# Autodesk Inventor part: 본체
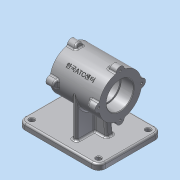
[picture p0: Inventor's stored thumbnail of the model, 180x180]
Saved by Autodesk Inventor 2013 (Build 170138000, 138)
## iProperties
Created: 2015-12
Part Number: 본체
Material: 알루미늄 6061
Document SubType Name: Modeling
Designer: dgall
Density: 2.71 g/cm^3
Mass: 1163.86 g
Surface Area: 818.799 cm^2
Volume: 429.47 cm^3
Author: dgall
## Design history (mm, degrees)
sketch "스케치1"
  geometry: C1 r 37 at (0, 0); 1 further point
  constraints: 1 centre point, 1 coincident
  dimensions: "d0" = 74 diameter of C1
extrude "돌출1" new body sketch "스케치1" stored distance "d1" = 85; taper "d2" = 0 deg
sketch "스케치2"
  geometry: L1 (0, 42.5)-(0, -42.5); L2 (0, 42.5)-(23.5, 42.5); L3 (23.5, 42.5)-(23.5, 20.5); L4 (23.5, 20.5)-(21, 20.5); L5 (21, 20.5)-(21, -20.5); L6 (21, -20.5)-(23.5, -20.5); L7 (23.5, -20.5)-(23.5, -42.5); L8 (23.5, -42.5)-(0, -42.5); 2 further points
  constraints: 16 end point, 4 parallel, 2 perpendicular, 1 coincident, 1 collinear, 1 midpoint, 1 vertical
  dimensions: "d3" = 85 distance of L1.start L1.end; "d5" = 47 diameter of L3 L1; "d6" = 47 diameter of L7 L1; "d7" = 42 diameter of L5 L1; "d8" = 22 distance of L2.end L3.end; "d9" = 22 distance of L6.end L7.end
revolve "회전1" sketch "스케치2" stored, may be unused: angle "d10" = 90 deg
sketch "스케치3"
  geometry: C1 r 23.5 at (0, 0) reference; C2 r 7 at (0, 37); 1 further point
  constraints: 2 vertical alignment, 1 centre point, 1 other
  dimensions: "d11" = 14 diameter of C2
node "작업 평면1"
sketch "스케치4"
  geometry: L1 (55, 80)-(-55, 80); L2 (-55, 80)-(-55, -60); L3 (-55, -60)-(55, -60); L4 (55, -60)-(55, 80); L5 (37, 4)-(-37, 4); L6 (-37, 4)-(-37, -4); L7 (-37, -4)-(37, -4); L8 (37, -4)-(37, 4); 5 further points
  constraints: 16 end point, 4 midpoint, 4 parallel, 2 horizontal, 2 perpendicular, 2 vertical alignment, 1 horizontal alignment
  dimensions: "d13" = 140 distance of L3.end L1.start; "d15" = 110 distance of L2.end L3.end; "d16" = 8 distance of L7.end L5.start; "d17" = 76 distance between parallel lines of L1 L5; "d18" = 74 distance of L6.end L7.end
extrude "돌출2" join sketch "스케치4" distance "d19" = 10; taper "d20" = 0 deg
extrude "돌출3" join sketch "스케치4" stored distance "d21" = 10; taper "d22" = 0 deg
sketch "스케치5"
  geometry: L1 (-70, -60)-(-70, 80) reference; L2 (-37, 20.948)-(-70, 25); L3 (-37, -20.948)-(-70, -25); L4 (37, 42.5)-(-37, 42.5) reference; 2 further points
  constraints: 4 end point, 2 point on line
  dimensions: "d24" = 50 distance of L3.end L2.end; "d25" = 21 distance of point (-70, 4) L2.end; "d26" = 97 deg angle of L1 L2; "d27" = 97 deg angle of L1 L3
feature "리브1" sketch "스케치5" dims "d28" = 1, "d29" = 12, "d30" = 0, "d31" = 0, "d32" = 1, "d33" = 1
node "작업 평면3"
extrude "돌출4" join sketch "스케치3" distance "d34" = 12.452; taper "d35" = 0 deg
sketch "스케치7"
  geometry: L1 (44, 42.5)-(44, 30.048) reference; L2 (37, -42.5)-(37, 30.048) reference; L3 (44, 30.048)-(34, 26.408); L4 (34, 30.5)-(44, 30.5); L5 (34, 30.5)-(34, 26.408); 2 further points
  constraints: 6 end point, 3 point on line, 2 perpendicular
  dimensions: "d41" = 110 deg angle of L2 L3; "d76" = 4.09191 distance of L4.start L3.end; "d78" = 10 distance of L4.start L4.end
extrude "돌출5" join sketch "스케치7" stored distance "d44" = 14; taper "d45" = 0 deg
sketch "스케치8"
  geometry: L1 (-9, 45)-(9, 45); L2 (9, 45)-(9, 35.889); L3 (-9, 35.889)-(-9, 45); C1 r 23.5 at (0, 0) reference; A1 r 7 centre (0, 37) between (6.969, 36.338) and (-6.969, 36.338) reference; A2 r 7 centre (0, 37) between (6.969, 36.338) and (-6.969, 36.338); A3 r 37 centre (0, 0) between (9, 35.889) and (6.969, 36.338); A4 r 37 centre (0, 0) between (-6.969, 36.338) and (-9, 35.889); 1 further point
  constraints: 6 end point, 6 point on circle, 3 centre point, 2 coincident, 1 horizontal, 1 parallel, 1 perpendicular, 1 vertical alignment
  dimensions: "d50" = 14 diameter of A2; "d51" = 18 distance of L1.start L1.end; "d54" = 9.11128 distance of L3.start L1.start; "d55" = 9.11128 distance of L1.end L2.end; "d57" = 37 radius of A4; "d58" = 37 radius of A3
extrude "돌출6" cut sketch "스케치8" distance "d59" = 20; taper "d60" = 0 deg
node "작업 평면4"
hole "구멍1" diameter "d66" = 3.459; stored, may be unused: countersink angle "d70" = 90 deg, drill point angle "d72" = 118 deg; dims "d64" = 10, "d65" = 10, "d67" = 9, "d68" = 4, "d69" = 2, "d71" = 11
fillet "모깎기1" dims "d79" = 12
hole "구멍2" diameter "d82" = 8; stored, may be unused: countersink angle "d86" = 90 deg, drill point angle "d88" = 0 deg; dims "d80" = 10, "d81" = 10, "d83" = 9, "d84" = 4, "d85" = 2, "d87" = 11
fillet "모깎기11" dims "d110" = 3
fillet "모깎기12" dims "d111" = 3
chamfer "모따기1" distance "d95" = 1; stored, may be unused: second distance "d96" = 2, angle "d97" = 45 deg
chamfer "모따기2" distance "d98" = 1; stored, may be unused: second distance "d99" = 2, angle "d100" = 45 deg
fillet "모깎기2" dims "d101" = 0.3
fillet "모깎기5" dims "d104" = 3
node "작업 평면6"
  node "작업 평면5"
sketch "스케치9"
  geometry: 2 further points
  constraints: 1 coincident, 1 other
feature "엠보싱1" sketch "스케치9" dims "d0" = 74, "d11" = 14, "d114" = 0.5, "d115" = 0
fillet "모깎기17" dims "d120" = 3
fillet "모깎기18" dims "d121" = 3
fillet "모깎기19" dims "d122" = 3
fillet "모깎기20" dims "d123" = 3
node "솔리드1"
mirror "대칭1"
pattern_circular "원형 패턴1" dims "d62" = 360 deg
mirror "대칭2"
pattern_circular "원형 패턴2" dims angle "d74" = 360 deg
mirror "대칭3"
pattern_linear "직사각형 패턴1" dims "d91" = 116, "d94" = 86
other parameters: "d49" = 2, "d56" = 74, "d112" = -45 deg, "d113" = 45
